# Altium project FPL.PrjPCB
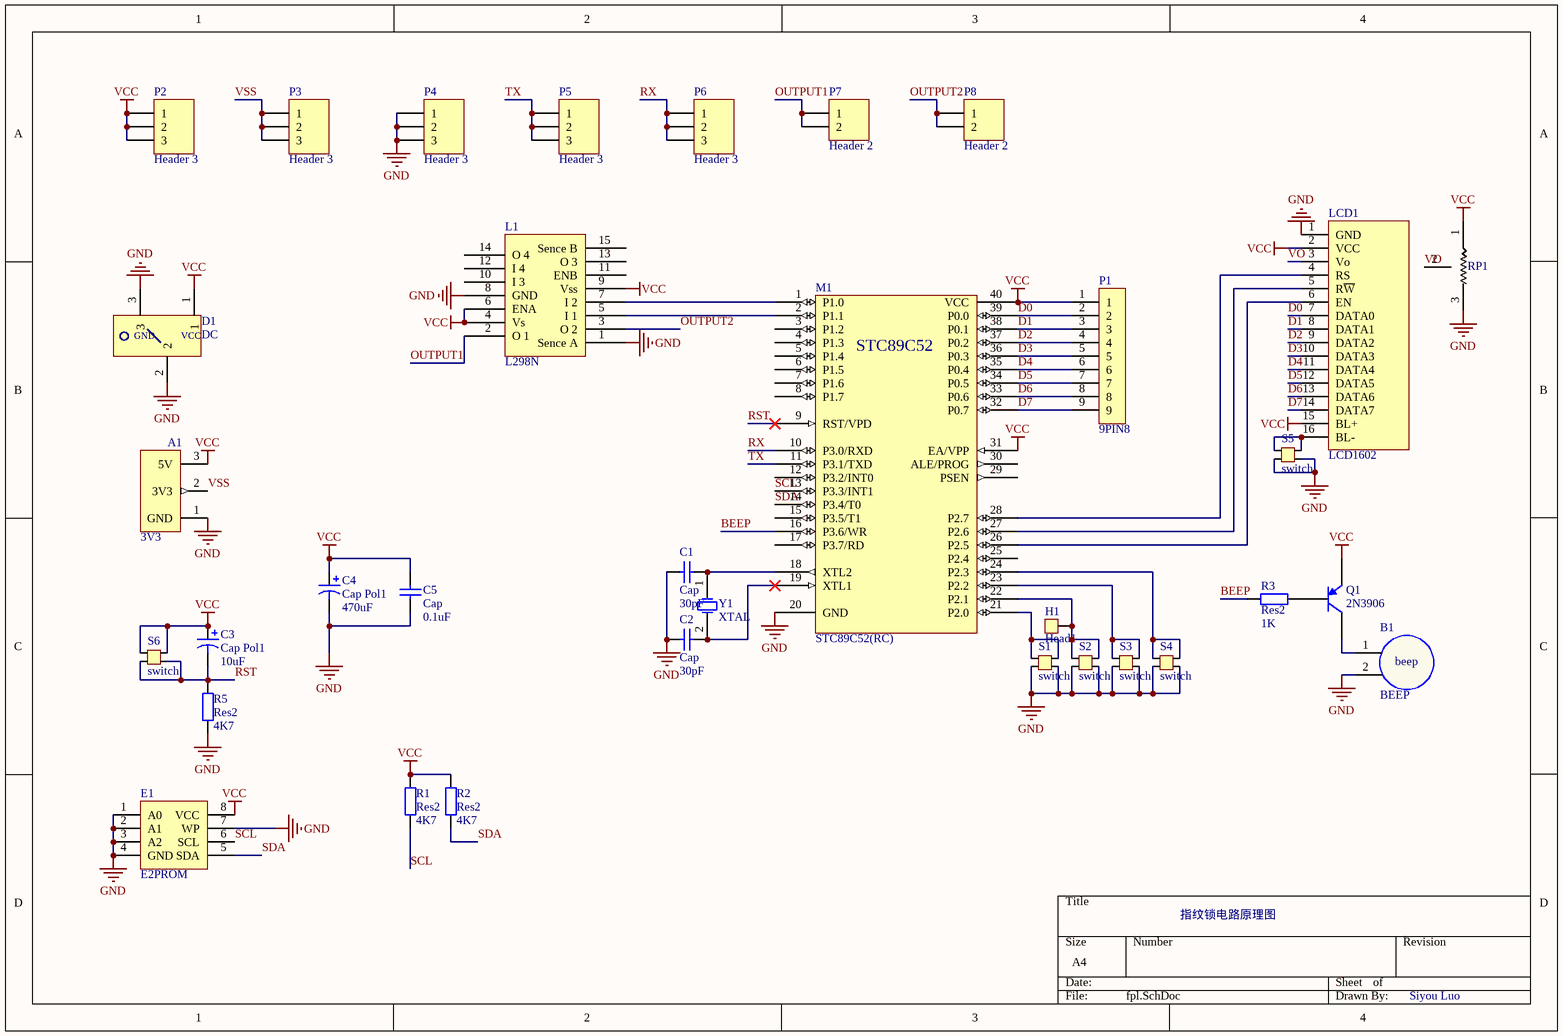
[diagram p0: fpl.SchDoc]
1 sheet, 34 parts. Net scope: global (net labels, ports and power ports of the same name join across sheets).
Board file: fpl.PcbDoc

## Sheet fpl.SchDoc: 指纹锁电路原理图
size A4; DrawnBy: Siyou Luo

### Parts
A1  3V3  [HDR1X3]
B1  BEEP  [BEEP]
C1  Cap  value 30pF  [RAD-0.1]
C2  Cap  value 30pF  [RAD-0.1]
C3  Cap Pol1  value 10uF  [ElecCap]
C4  Cap Pol1  value 470uF  [ElecCap470]
C5  Cap  value 0.1uF  [RAD-0.1]
D1  DC  [DC005]
E1  E2PROM  [DIP-8]
H1  Head1  [Head1]
L1  L298N  [Multiwatt15V]
LCD1  LCD1602  [1602]
M1  STC89C52(RC)
P1  9PIN8  [HDR1X9]
P2  Header 3  [HDR1X3]
P3  Header 3  [HDR1X3]
P4  Header 3  [HDR1X3]
P5  Header 3  [HDR1X3]
P6  Header 3  [HDR1X3]
P7  Header 2  [HDR1X2]
P8  Header 2  [HDR1X2]
Q1  2N3906  [BCY-W3/E4]
R1  Res2  value 4K7  [AXIAL-0.3]
R2  Res2  value 4K7  [AXIAL-0.3]
R3  Res2  value 1K  [AXIAL-0.3]
R5  Res2  value 4K7  [AXIAL-0.3]
RP1  potentiometer  [potentionmeter]  (value not drawn)
S1  switch  [switch_4pin]
S2  switch  [switch_4pin]
S3  switch  [switch_4pin]
S4  switch  [switch_4pin]
S5  switch  [switch_4pin]
S6  switch  [switch_4pin]
Y1  XTAL  [XTAL]

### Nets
GND: A1.1(GND) B1.2 C1.1 C2.1 C4.2 C5.2 D1.2 D1.3 E1.1(A0) E1.2(A1) E1.3(A2) E1.4(GND) E1.7(WP) L1.1(Sence_A) L1.8(GND) LCD1.1(GND) M1.20(GND) P4.1 P4.2 P4.3 R5.1 RP1.3 S1.1 S1.3 S2.1 S2.3 S3.1 S3.3 S4.1 S4.3 S5.1 S5.3
VCC: A1.3(5V) C3.1 C4.1 C5.1 D1.1 E1.8(VCC) L1.4(Vs) L1.6(ENA) L1.9(Vss) LCD1.2(VCC) LCD1.15(BL+) M1.31(EA/VPP) M1.40(VCC) P1.1 P2.1 P2.2 P2.3 Q1.1(E) R1.2 R2.2 RP1.1 S6.0 S6.2
BEEP: M1.16(P3.6/WR) R3.1
D0: LCD1.7(DATA0) M1.39(P0.0) P1.2
D1: LCD1.8(DATA1) M1.38(P0.1) P1.3
D2: LCD1.9(DATA2) M1.37(P0.2) P1.4
D3: LCD1.10(DATA3) M1.36(P0.3) P1.5
D4: LCD1.11(DATA4) M1.35(P0.4) P1.6
D5: LCD1.12(DATA5) M1.34(P0.5) P1.7
D6: LCD1.13(DATA6) M1.33(P0.6) P1.8
D7: LCD1.14(DATA7) M1.32(P0.7) P1.9
OUTPUT1: L1.2(O_1) P7.1 P7.2
OUTPUT2: L1.3(O_2) P8.1 P8.2
RST: C3.2 M1.9(RST/VPD) R5.2 S6.1 S6.3
RX: M1.10(P3.0/RXD) P6.1 P6.2 P6.3
SCL: E1.6(SCL) M1.13(P3.3/INT1) R1.1
SDA: E1.5(SDA) M1.14(P3.4/T0) R2.1
TX: M1.11(P3.1/TXD) P5.1 P5.2 P5.3
VO: LCD1.3(Vo) RP1.2
VSS: A1.2(3V3) P3.1 P3.2 P3.3
NetB1_1: B1.1 Q1.3(C)
NetC1_2: C1.2 M1.18(XTL2) Y1.1(OSC1)
NetC2_2: C2.2 M1.19(XTL1) Y1.2(OSC2)
NetH1_1: H1.1(H?) M1.22(P2.1) S2.0 S2.2
NetL1_5: L1.5(I_1) M1.2(P1.1)
NetL1_7: L1.7(I_2) M1.1(P1.0)
NetLCD1_4: LCD1.4(RS) M1.28(P2.7)
NetLCD1_5: LCD1.5(R~{W}) M1.27(P2.6)
NetLCD1_6: LCD1.6(EN) M1.26(P2.5)
NetLCD1_16: LCD1.16(BL-) S5.0 S5.2
NetM1_21: M1.21(P2.0) S1.0 S1.2
NetM1_23: M1.23(P2.2) S3.0 S3.2
NetM1_24: M1.24(P2.3) S4.0 S4.2
NetQ1_2: Q1.2(B) R3.2

Not connected (* = marked no-connect by the designer): L1 10(I_3) 11(ENB) 12(I_4) 13(O_3) 14(O_4) 15(Sence_B); M1 3(P1.2) 4(P1.3) 5(P1.4) 6(P1.5) 7(P1.6) 8(P1.7) 12(P3.2/INT0) 15(P3.5/T1) 17(P3.7/RD) 25(P2.4) 29(PSEN) 30(ALE/PROG)

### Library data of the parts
A1 = AMS1117: 3.3V电源模块, 5V to 3.3V
B1 = BEEP: 蜂鸣器
C1 C2 C5 = Cap: Capacitor
C3 C4 = Cap Pol1: Polarized Capacitor (Radial)
D1 = DC: DC插座
E1 = AT24C02: E2PROM,I2C-上拉
H1 = Head1: 1pin焊盘
L1 = L298N: 电机驱动芯片
M1 = STC89C52: MCU
P1 = 9PIN8: 9PIN8排阻
P2-P6 = Header 3: Header, 3-Pin
P7 P8 = Header 2: Header, 2-Pin
Q1 = 2N3906: PNP General Purpose Amplifier
R1-R3 R5 = Res2: Resistor
RP1 = 电位计: 旋钮式电位计
S1-S6 = Switch_4pin: 单稳态按钮开关
Y1 = XTAL: Crystal Oscillator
